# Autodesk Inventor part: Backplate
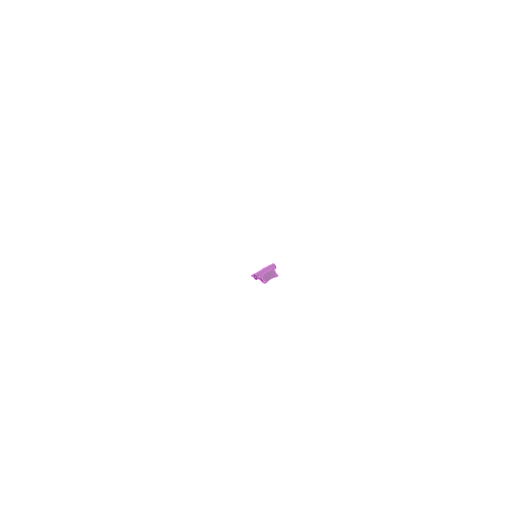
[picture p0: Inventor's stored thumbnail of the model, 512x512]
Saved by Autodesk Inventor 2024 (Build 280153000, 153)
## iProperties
Created: 2024-06
Part Number: Backplate
Material: PET Plastic
Document SubType Name: Modeling
Designer: simon
Density: 1.541 g/cm^3
Appearance: Smooth - Purple
Author: simon
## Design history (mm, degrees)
sketch "Sketch1"
  geometry: L1 (62.5, 62.5)-(-62.5, 62.5); L2 (-62.5, 62.5)-(-62.5, -62.5); L3 (-62.5, -62.5)-(62.5, -62.5); L4 (62.5, 62.5)-(-62.5, -62.5); L5 (-62.5, 62.5)-(62.5, -62.5); L6 (52.5, 62.5)-(52.5, -62.5); L7 (62.5, -52.5)-(-62.5, -52.5); L8 (0, 62.5)-(0, -62.5); L9 (-62.5, 0)-(62.5, 0); L10 (62.5, 62.5)-(-62.5, -62.5); A1 r 113.114 centre (165.614, 0) between (52.5, 0) and (61.452, -44.104); A2 r 113.114 centre (0, -165.614) between (44.104, -61.452) and (0, -52.5); A3 r 13.236 centre (49.264, -49.264) between (44.104, -61.452) and (61.452, -44.104); A4 r 113.114 centre (165.614, 0) between (61.452, 44.104) and (52.5, 0); A5 r 13.236 centre (49.264, 49.264) between (61.452, 44.104) and (44.104, 61.452); A6 r 113.114 centre (0, 165.614) between (0, 52.5) and (44.104, 61.452); A7 r 13.236 centre (-49.264, 49.264) between (-44.104, 61.452) and (-61.452, 44.104); A8 r 113.114 centre (0, 165.614) between (-44.104, 61.452) and (0, 52.5); A9 r 113.114 centre (-165.614, 0) between (-52.5, 0) and (-61.452, 44.104); A10 r 113.114 centre (-165.614, 0) between (-61.452, -44.104) and (-52.5, 0); A11 r 13.236 centre (-49.264, -49.264) between (-61.452, -44.104) and (-44.104, -61.452); A12 r 113.114 centre (0, -165.614) between (0, -52.5) and (-44.104, -61.452); 1 further point; 1 other entity
  constraints: 24 point on circle, 20 end point, 13 symmetric about line, 12 centre point, 7 midpoint, 5 tangent, 3 point on line, 2 perpendicular, 2 vertical, 1 horizontal, 1 parallel, 15 other
  dimensions: "d2" = 10 dimension on L6; "d3" = 10 distance between parallel lines of L3 L7; "d29" = 125 distance of L3.end L1.start; "d30" = 125 distance of L2.end L3.end
workplane "Work Plane1"
sketch "Sketch2"
  geometry: L1 (-17.5, 80)-(17.5, 80); L2 (17.5, 80)-(17.5, -80); L3 (17.5, -80)-(-17.5, -80); L4 (-17.5, -80)-(-17.5, 80); L5 (-17.5, 80)-(17.5, -80); L6 (17.5, 80)-(-17.5, -80); 1 further point
  constraints: 12 end point, 2 midpoint, 2 parallel, 1 horizontal, 1 perpendicular
  dimensions: "d6" = 35 distance of L2.end L3.end; "d7" = 160 distance of L1.end L2.end
loft "Loft1" sketch "Sketch2" dims "d8" = 0, "d9" = 90 deg, "d10" = 0, "d11" = 90 deg
sketch "Sketch3"
  geometry: L1 (-17.5, 40)-(17.5, 40) reference; L2 (0, -9.031)-(0, 54.187) reference; 4 further points; 1 other entity
  constraints: 1 midpoint, 1 point on line, 3 other
  dimensions: "d33" = 10 distance of point (0, 30) point (0, 40)
extrude "Extrusion1" join sketch "Sketch3" stored distance "d12" = 160 (= d7); taper "d13" = 0 deg
fillet "Fillet1" dims "d19" = 50
sketch "Sketch5"
  geometry: C1 r 4 at (0, 30); 8 further points; 1 other entity
  constraints: 1 centre point, 1 coincident, 1 other
  dimensions: "d16" = 8 diameter of C1
extrude "Extrusion3" cut sketch "Sketch5" extent not by distance; stored distance "d17" = 0; taper "d18" = 0 deg
sketch "Sketch7"
  geometry: L1 (0, -160.655)-(0, 186.055) reference; L2 (84.138, 0)-(-77.788, 0); L3 (0, -111.125)-(0, 136.525); C1 r 2.5 at (50, 50); C2 r 2.5 at (50, -50); C3 r 2.5 at (-50, -50); C4 r 2.5 at (-50, 50); 1 further point
  constraints: 4 centre point, 4 end point, 3 symmetric about line, 2 point on line, 1 horizontal, 3 other
  dimensions: "d20" = 5 diameter of C1; "d21" = 50 horizontal distance of point (0, 0) C1.centre; "d22" = 50 distance from line of L1 C1.centre
extrude "Extrusion4" cut sketch "Sketch7" extent not by distance; stored distance "d23" = 0; taper "d24" = 0 deg
workplane "Work Plane2"
sketch "Sketch8"
  geometry: C1 r 2.5 at (50, 50) reference; C2 r 5 at (50, 50); C3 r 2.5 at (50, -50) reference; C4 r 5 at (50, -50); C5 r 2.5 at (-50, -50) reference; C6 r 5 at (-50, -50); C7 r 2.5 at (-50, 50) reference; C8 r 5 at (-50, 50); 1 further point
  constraints: 4 centre point, 4 coincident, 3 equal radius
  dimensions: "d26" = 10 diameter of C2
extrude "Extrusion5" cut sketch "Sketch8" distance "d27" = 28; taper "d28" = 0 deg
fillet "Fillet4" dims "d34" = 10
body "Solid1"
other parameters: "d25" = 33.3375
